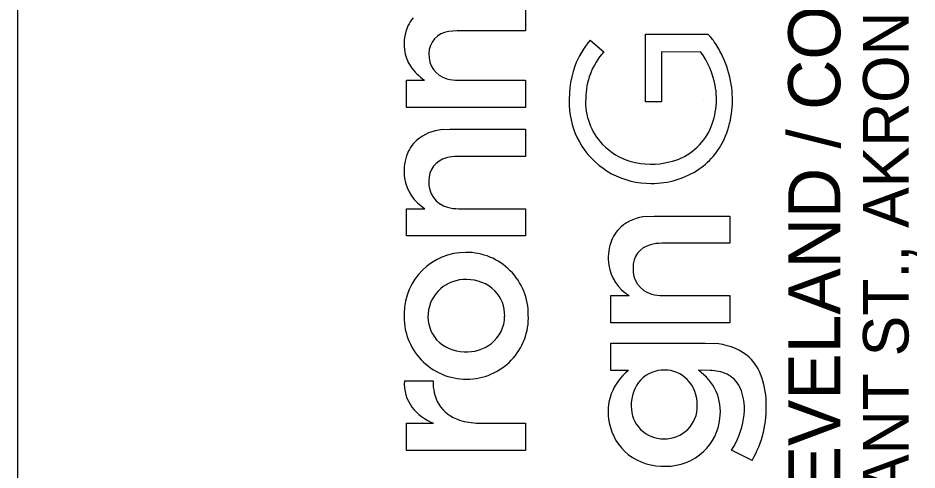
# Model space of a CAD drawing. Extents: x -0.6 to 34, y 0 to 22.
# Drawn here: x 32 to 32.984, y 3.094 to 3.59 of the extents above; entities that cross this region are included whole.
import ezdxf

# ---------------------------------------------------------------- set-up
doc = ezdxf.new("R2010")
doc.units = 0
doc.layers.add('SH_Cut_Line', color=7, linetype='Continuous')
doc.layers.add('SH_Data', color=7, linetype='Continuous')

msp = doc.modelspace()

# ---------------------------------------------------------------- linework, layer by layer
at = {"layer": 'SH_Cut_Line'}
for p, q in [((32.55571, 3.60548), (32.55571, 3.57568)), ((32.4809, 3.57567), (32.47143, 3.57474)), ((32.55571, 3.57568), (32.4809, 3.57567)), ((32.62636, 3.56548), (32.64114, 3.55241)), ((32.6868, 3.57185), (32.75516, 3.57192)), ((32.6868, 3.49778), (32.6868, 3.57185)), ((32.70448, 3.55241), (32.70432, 3.49775)), ((32.74737, 3.55227), (32.70448, 3.55241)), ((32.42542, 3.49152), (32.42545, 3.52138)), ((32.42545, 3.52138), (32.44515, 3.52138)), ((32.48206, 3.52138), (32.55571, 3.52136)), ((32.55571, 3.52136), (32.55571, 3.49156)), ((32.70432, 3.49775), (32.6868, 3.49778)), ((32.75, 3.5), (32.75, 3.5)), ((32.55571, 3.49156), (32.42542, 3.49152)), ((32.46439, 3.46736), (32.47289, 3.46783)), ((32.47289, 3.46783), (32.55571, 3.46783)), ((32.55571, 3.46783), (32.55571, 3.43804)), ((32.55571, 3.43804), (32.4814, 3.43796)), ((32.42542, 3.38066), (32.44552, 3.38071)), ((32.42542, 3.35086), (32.42542, 3.38066)), ((32.48222, 3.38071), (32.55569, 3.38071)), ((32.55569, 3.38071), (32.55571, 3.35096)), ((32.68784, 3.3722), (32.69634, 3.37266)), ((32.69634, 3.37266), (32.77916, 3.37266)), ((32.77916, 3.37266), (32.77917, 3.34287)), ((32.55571, 3.35096), (32.42542, 3.35086)), ((32.77917, 3.34287), (32.70485, 3.3428)), ((32.64888, 3.2855), (32.66897, 3.28555)), ((32.64888, 3.25569), (32.64888, 3.2855)), ((32.70568, 3.28555), (32.77915, 3.28555)), ((32.77915, 3.28555), (32.77917, 3.25579)), ((32.77917, 3.25579), (32.64888, 3.25569)), ((32.6489, 3.20336), (32.64889, 3.23322)), ((32.64889, 3.23322), (32.75236, 3.23322)), ((32.75236, 3.23322), (32.76191, 3.23285)), ((32.66836, 3.20336), (32.6489, 3.20336)), ((32.75763, 3.20356), (32.74487, 3.20361)), ((32.42299, 3.19193), (32.45454, 3.19193)), ((32.42542, 3.14577), (32.45473, 3.14579)), ((32.42542, 3.11593), (32.42542, 3.14577)), ((32.50413, 3.14581), (32.55571, 3.14573)), ((32.55571, 3.14573), (32.55565, 3.11593)), ((32.55565, 3.11593), (32.42542, 3.11593)), ((32.8036, 3.10491), (32.7812, 3.11598))]:
    msp.add_line(p, q, dxfattribs=at)
for points in [[(32.48218, 3.60553), (32.55571, 3.60548), (32.55571, 3.57568), (32.4809, 3.57567), (32.47143, 3.57474)], [(32.62636, 3.56548), (32.64114, 3.55241)], [(32.74737, 3.55227), (32.70448, 3.55241), (32.70432, 3.49775), (32.6868, 3.49778), (32.6868, 3.57185), (32.75516, 3.57192)], [(32.42542, 3.49152), (32.42545, 3.52138), (32.44515, 3.52138)], [(32.48206, 3.52138), (32.55571, 3.52136), (32.55571, 3.49156), (32.42542, 3.49152)], [(32.46439, 3.46736), (32.47289, 3.46783), (32.55571, 3.46783), (32.55571, 3.43804), (32.4814, 3.43796)], [(32.42542, 3.35086), (32.42542, 3.38066), (32.44552, 3.38071)], [(32.48222, 3.38071), (32.55569, 3.38071), (32.55571, 3.35096), (32.42542, 3.35086)], [(32.68784, 3.3722), (32.69634, 3.37266), (32.77916, 3.37266), (32.77917, 3.34287), (32.70485, 3.3428)], [(32.64888, 3.25569), (32.64888, 3.2855), (32.66897, 3.28555)], [(32.70568, 3.28555), (32.77915, 3.28555), (32.77917, 3.25579), (32.64888, 3.25569)], [(32.66836, 3.20336), (32.6489, 3.20336), (32.64889, 3.23322), (32.75236, 3.23322), (32.76191, 3.23285)], [(32.75763, 3.20356), (32.74487, 3.20361)], [(32.42299, 3.19193), (32.45454, 3.19193)], [(32.50413, 3.14581), (32.55571, 3.14573), (32.55565, 3.11593), (32.42542, 3.11593)], [(32.42542, 3.11593), (32.42542, 3.14577), (32.45473, 3.14579)], [(32.8036, 3.10491), (32.7812, 3.11598)]]:
    msp.add_lwpolyline(points, dxfattribs=at)
for centre, radius, start, end in [((32.46194, 3.56452), 0.03875, 139.52447, 154.84698), ((32.46194, 3.56452), 0.03875, 139.52447, 154.84698), ((32.47144, 3.5612), 0.04877, 156.06382, 187.3493), ((32.47144, 3.5612), 0.04877, 156.06382, 187.3493), ((32.47421, 3.55056), 0.02434, 96.5532, 179.94902), ((32.47421, 3.55056), 0.02434, 96.5532, 179.94902), ((32.70163, 3.50187), 0.09855, 139.79476, 159.13696), ((32.70163, 3.50187), 0.09855, 139.79476, 159.13696), ((32.72498, 3.53937), 0.04438, 30.98913, 47.16099), ((32.72498, 3.53937), 0.04438, 30.98913, 47.16099), ((32.46461, 3.55974), 0.04181, 186.5579, 213.38846), ((32.46461, 3.55974), 0.04181, 186.5579, 213.38846), ((32.67091, 3.50018), 0.11106, 25.30315, 33.96179), ((32.67091, 3.50018), 0.11106, 25.30315, 33.96179), ((32.47608, 3.54863), 0.02628, 175.722, 255.78627), ((32.47608, 3.54863), 0.02628, 175.722, 255.78627), ((32.69899, 3.50079), 0.07753, 138.25804, 179.70064), ((32.69899, 3.50079), 0.07753, 138.25804, 179.70064), ((32.67889, 3.50099), 0.08556, 10.07509, 36.83189), ((32.67889, 3.50099), 0.08556, 10.07509, 36.83189), ((32.6704, 3.49987), 0.11166, 8.80339, 25.33484), ((32.6704, 3.49987), 0.11166, 8.80339, 25.33484), ((32.47886, 3.57078), 0.0598, 214.70433, 235.68724), ((32.47886, 3.57078), 0.0598, 214.70433, 235.68724), ((32.7187, 3.49968), 0.11536, 161.14379, 185.62812), ((32.7187, 3.49968), 0.11536, 161.14379, 185.62812), ((32.48195, 3.56518), 0.0438, 253.66719, 270.14979), ((32.48195, 3.56518), 0.0438, 253.66719, 270.14979), ((32.68425, 3.50057), 0.08036, 333.46689, 11.03668), ((32.68425, 3.50057), 0.08036, 333.46689, 11.03668), ((32.67564, 3.49977), 0.10649, 338.28866, 9.28548), ((32.67564, 3.49977), 0.10649, 338.28866, 9.28548), ((32.68811, 3.49732), 0.06676, 176.66577, 223.6912), ((32.68811, 3.49732), 0.06676, 176.66577, 223.6912), ((32.69336, 3.49699), 0.08987, 185.50773, 212.01294), ((32.69336, 3.49699), 0.08987, 185.50773, 212.01294), ((32.46871, 3.41767), 0.04988, 94.97056, 130.22484), ((32.46871, 3.41767), 0.04988, 94.97056, 130.22484), ((32.69868, 3.49547), 0.0652, 282.88151, 331.81475), ((32.69868, 3.49547), 0.0652, 282.88151, 331.81475), ((32.46348, 3.42602), 0.04016, 132.22383, 161.68229), ((32.46348, 3.42602), 0.04016, 132.22383, 161.68229), ((32.69835, 3.49168), 0.08241, 305.03061, 337.67573), ((32.69835, 3.49168), 0.08241, 305.03061, 337.67573), ((32.69211, 3.49748), 0.08908, 212.70222, 270.71399), ((32.69211, 3.49748), 0.08908, 212.70222, 270.71399), ((32.69045, 3.50011), 0.07039, 224.02147, 253.88), ((32.69045, 3.50011), 0.07039, 224.02147, 253.88), ((32.47872, 3.42158), 0.05602, 162.27398, 187.79173), ((32.47872, 3.42158), 0.05602, 162.27398, 187.79173), ((32.47482, 3.41206), 0.02498, 103.68683, 182.21395), ((32.47482, 3.41206), 0.02498, 103.68683, 182.21395), ((32.48108, 3.39196), 0.04601, 89.60515, 105.33026), ((32.48108, 3.39196), 0.04601, 89.60515, 105.33026), ((32.69318, 3.51254), 0.08309, 254.45353, 283.9512), ((32.69318, 3.51254), 0.08309, 254.45353, 283.9512), ((32.69429, 3.49979), 0.09138, 269.3273, 304.19632), ((32.69429, 3.49979), 0.09138, 269.3273, 304.19632), ((32.47027, 3.42141), 0.04763, 188.96462, 238.69865), ((32.47027, 3.42141), 0.04763, 188.96462, 238.69865), ((32.47735, 3.40897), 0.02757, 175.58441, 255.13816), ((32.47735, 3.40897), 0.02757, 175.58441, 255.13816), ((32.48183, 3.42286), 0.04215, 254.08913, 270.52838), ((32.48183, 3.42286), 0.04215, 254.08913, 270.52838), ((32.69216, 3.32251), 0.04988, 94.97056, 130.22484), ((32.69216, 3.32251), 0.04988, 94.97056, 130.22484), ((32.68694, 3.33085), 0.04016, 132.22383, 161.68229), ((32.68694, 3.33085), 0.04016, 132.22383, 161.68229), ((32.70217, 3.32642), 0.05602, 162.27398, 187.79173), ((32.70217, 3.32642), 0.05602, 162.27398, 187.79173), ((32.69828, 3.31689), 0.02498, 103.68683, 182.21395), ((32.69828, 3.31689), 0.02498, 103.68683, 182.21395), ((32.70453, 3.29679), 0.04601, 89.60515, 105.33026), ((32.70453, 3.29679), 0.04601, 89.60515, 105.33026), ((32.49014, 3.26543), 0.0674, 89.84756, 179.64047), ((32.49014, 3.26543), 0.0674, 89.84756, 179.64047), ((32.49057, 3.26474), 0.0681, 359.54009, 90.21138), ((32.49057, 3.26474), 0.0681, 359.54009, 90.21138), ((32.69372, 3.32624), 0.04763, 188.96462, 238.69865), ((32.69372, 3.32624), 0.04763, 188.96462, 238.69865), ((32.7008, 3.31381), 0.02757, 175.58441, 255.13816), ((32.7008, 3.31381), 0.02757, 175.58441, 255.13816), ((32.48923, 3.26263), 0.0404, 87.04809, 175.57259), ((32.48923, 3.26263), 0.0404, 87.04809, 175.57259), ((32.49204, 3.25999), 0.04299, 45.84264, 90.98008), ((32.49204, 3.25999), 0.04299, 45.84264, 90.98008), ((32.49458, 3.26421), 0.03821, 357.88569, 44.15902), ((32.49458, 3.26421), 0.03821, 357.88569, 44.15902), ((32.70529, 3.32769), 0.04215, 254.08913, 270.52838), ((32.70529, 3.32769), 0.04215, 254.08913, 270.52838), ((32.49083, 3.26209), 0.06819, 176.8344, 270.40384), ((32.49083, 3.26209), 0.06819, 176.8344, 270.40384), ((32.48729, 3.2625), 0.03848, 175.15378, 221.14706), ((32.48729, 3.2625), 0.03848, 175.15378, 221.14706), ((32.49123, 3.26139), 0.06749, 270.06243, 2.37759), ((32.49123, 3.26139), 0.06749, 270.06243, 2.37759), ((32.49446, 3.26318), 0.0383, 308.28936, 359.43468), ((32.49446, 3.26318), 0.0383, 308.28936, 359.43468), ((32.48919, 3.26607), 0.04228, 223.09994, 268.80895), ((32.48919, 3.26607), 0.04228, 223.09994, 268.80895), ((32.49096, 3.2679), 0.04418, 266.56515, 308.06078), ((32.49096, 3.2679), 0.04418, 266.56515, 308.06078), ((32.75907, 3.16789), 0.06503, 53.40344, 87.49062), ((32.75907, 3.16789), 0.06503, 53.40344, 87.49062), ((32.76517, 3.18039), 0.05141, 21.60748, 50.5577), ((32.76517, 3.18039), 0.05141, 21.60748, 50.5577), ((32.70292, 3.15813), 0.05692, 127.37482, 192.22468), ((32.70292, 3.15813), 0.05692, 127.37482, 192.22468), ((32.70693, 3.16927), 0.0346, 88.47302, 136.42562), ((32.70693, 3.16927), 0.0346, 88.47302, 136.42562), ((32.70814, 3.16963), 0.03424, 44.27195, 90.47623), ((32.70814, 3.16963), 0.03424, 44.27195, 90.47623), ((32.71421, 3.15829), 0.05472, 352.1125, 55.92295), ((32.71421, 3.15829), 0.05472, 352.1125, 55.92295), ((32.75666, 3.15725), 0.04633, 65.01687, 88.8011), ((32.75666, 3.15725), 0.04633, 65.01687, 88.8011), ((32.7626, 3.17155), 0.03085, 26.26808, 63.80301), ((32.7626, 3.17155), 0.03085, 26.26808, 63.80301), ((32.73069, 3.16714), 0.08835, 1.15143, 21.3627), ((32.73069, 3.16714), 0.08835, 1.15143, 21.3627), ((32.46616, 3.18882), 0.04329, 175.87313, 216.34747), ((32.46616, 3.18882), 0.04329, 175.87313, 216.34747), ((32.50087, 3.18948), 0.04639, 176.9688, 209.60636), ((32.50087, 3.18948), 0.04639, 176.9688, 209.60636), ((32.71141, 3.16602), 0.0401, 137.46739, 182.33237), ((32.71141, 3.16602), 0.0401, 137.46739, 182.33237), ((32.70368, 3.166), 0.03996, 358.57141, 43.53765), ((32.70368, 3.166), 0.03996, 358.57141, 43.53765), ((32.73565, 3.16154), 0.05953, 349.30734, 23.43071), ((32.73565, 3.16154), 0.05953, 349.30734, 23.43071), ((32.47466, 3.19716), 0.05511, 218.09809, 248.7907), ((32.47466, 3.19716), 0.05511, 218.09809, 248.7907), ((32.49514, 3.18814), 0.04079, 211.94466, 253.2028), ((32.49514, 3.18814), 0.04079, 211.94466, 253.2028), ((32.70645, 3.1637), 0.03511, 178.88208, 271.08374), ((32.70645, 3.1637), 0.03511, 178.88208, 271.08374), ((32.70818, 3.16404), 0.03546, 268.27882, 1.55016), ((32.70818, 3.16404), 0.03546, 268.27882, 1.55016), ((32.70538, 3.16244), 0.11383, 329.6388, 3.25998), ((32.70538, 3.16244), 0.11383, 329.6388, 3.25998), ((32.70988, 3.15708), 0.05887, 313.74196, 353.8554), ((32.70988, 3.15708), 0.05887, 313.74196, 353.8554), ((32.70738, 3.16334), 0.08771, 327.31495, 351.57478), ((32.70738, 3.16334), 0.08771, 327.31495, 351.57478), ((32.50465, 3.2165), 0.07069, 252.46555, 269.57296), ((32.50465, 3.2165), 0.07069, 252.46555, 269.57296), ((32.70463, 3.15696), 0.05837, 190.75182, 231.28919), ((32.70463, 3.15696), 0.05837, 190.75182, 231.28919), ((32.70632, 3.16112), 0.06269, 232.46061, 272.59022), ((32.70632, 3.16112), 0.06269, 232.46061, 272.59022), ((32.70954, 3.15901), 0.06051, 269.6361, 312.70877), ((32.70954, 3.15901), 0.06051, 269.6361, 312.70877)]:
    msp.add_arc(centre, radius, start, end, dxfattribs=at)
at = {"layer": 'SH_Data'}
msp.add_line((32, 0.5), (32, 21.5), dxfattribs=at)

# ---------------------------------------------------------------- texts
at = {"layer": 'SH_Cut_Line'}
for s, height, p in [('450 GRANT ST., AKRON, OH  44311', 0.0498462, (32.97489, 2.83738)), ('AKRON / CLEVELAND / COLUMBUS', 0.056969, (32.90012, 2.638))]:
    msp.add_text(s, height=height, rotation=90, dxfattribs=at).set_placement(p)

doc.saveas('drawing.dxf')
